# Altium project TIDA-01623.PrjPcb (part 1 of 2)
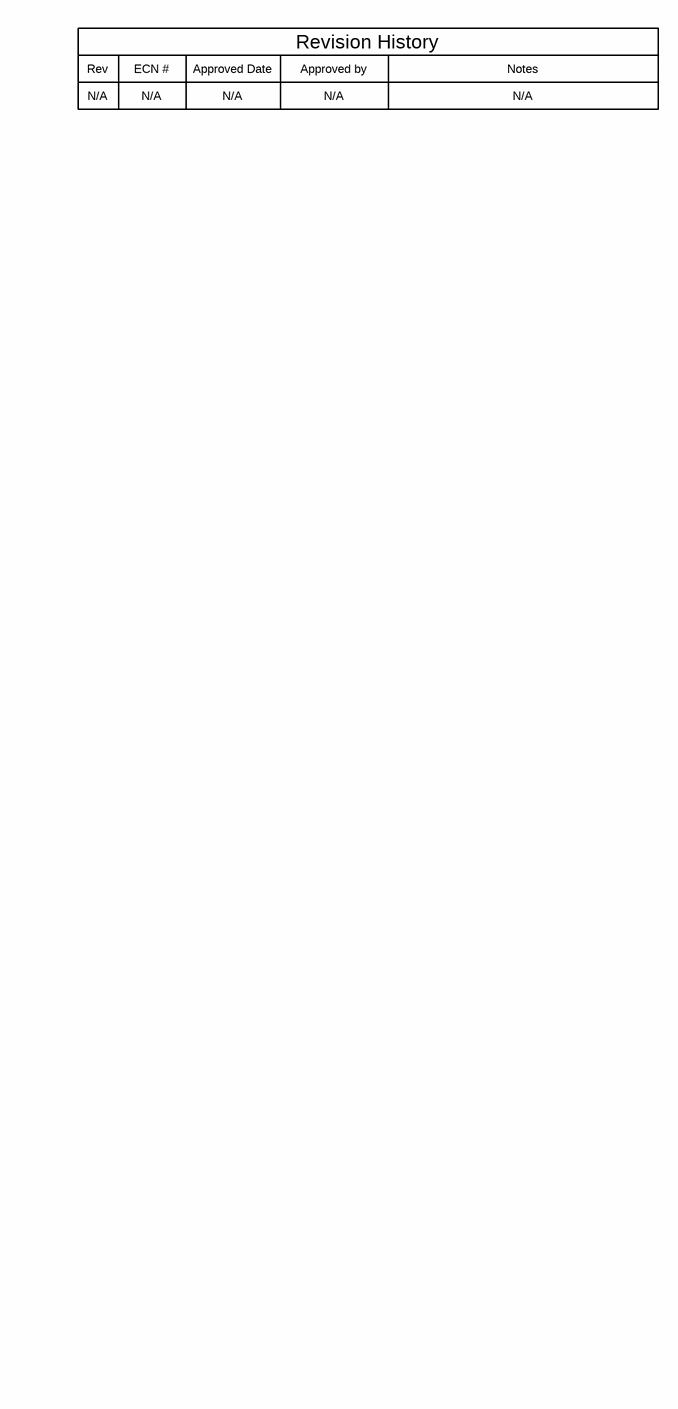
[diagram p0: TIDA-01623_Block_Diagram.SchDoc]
CopyrightYear: 2017; EVM_orderable: N/A; PCB_Layout: Akshay Labhe; PCB_Rev: E1; PRJ_Customer: Public Release; PRJ_Engineer: Cheng Liu; PRJ_Number: TIDA-01623; PRJ_Title: 100W AC/DC Adapter; SCH_Rev: E1; TechSupport: http://www.ti.com/support; TID: TIDA-01623
4 sheets, 214 parts. Net scope: flat (ports and power ports of the same name join across sheets).
Board file: TIDA-01623.PcbDoc
Sheets:
  TIDA-01623_Block_Diagram.SchDoc
  TIDA-01623_PFC_Stage.SchDoc
  TIDA-01623-ACF_Stage.SchDoc
  TIDA-01623_Hardware.SchDoc

## Sheet TIDA-01623_Block_Diagram.SchDoc: Block Diagram
size 431 x 279 mm; Date: Not shown in title block; ApprovedBy: Not shown in title block; CheckedBy: Not shown in title block; Author: Not shown in title block; CompanyName: Not shown in title block; DrawnBy: Cheng Liu; Engineer: Cheng Liu; Organization: Not shown in title block; Address1: Not shown in title block; Address2: Not shown in title block; Address3: Not shown in title block; Address4: Not shown in title block; DocumentNumber: 1; Revision: Use project parameter SCH_Rev; SheetNumber: 1; SheetTotal: 4; PageSetup: Record=PageOptions¦CenterHorizontal=True¦CenterVertical=True¦PrintScale=1.00¦XCorrection=1.00¦YCorrection=1.00¦PrintKind=0¦BorderSize=5000000¦LeftOffset=0¦BottomOffset=0¦Orientation=2¦PaperLength=1000¦PaperWidth=1000¦Scale=100¦PaperSource=15¦PrintQuality=600¦MediaType=1¦DitherType=10¦PaperKind=Letter¦PrintScaleMode=1

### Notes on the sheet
- Rev
- N/A
- ECN #
- Approved Date
- Approved by
- Revision History
- Notes

## Sheet TIDA-01623_PFC_Stage.SchDoc
size 431 x 279 mm; Date: Not shown in title block; ApprovedBy: Not shown in title block; CheckedBy: Not shown in title block; Author: Not shown in title block; CompanyName: Not shown in title block; Engineer: Not shown in title block; Organization: Not shown in title block; Address1: Not shown in title block; Address2: Not shown in title block; Address3: Not shown in title block; Address4: Not shown in title block; DocumentNumber: 1; Revision: Use project parameter SCH_Rev; SheetNumber: 2; SheetTotal: 4; PageSetup: Record=PageOptions¦CenterHorizontal=True¦CenterVertical=True¦PrintScale=1.00¦XCorrection=1.00¦YCorrection=1.00¦PrintKind=0¦BorderSize=5000000¦LeftOffset=0¦BottomOffset=0¦Orientation=2¦PaperLength=1000¦PaperWidth=1000¦Scale=100¦PaperSource=15¦PrintQuality=600¦MediaType=1¦DitherType=10¦PaperKind=Letter¦PrintScaleMode=1
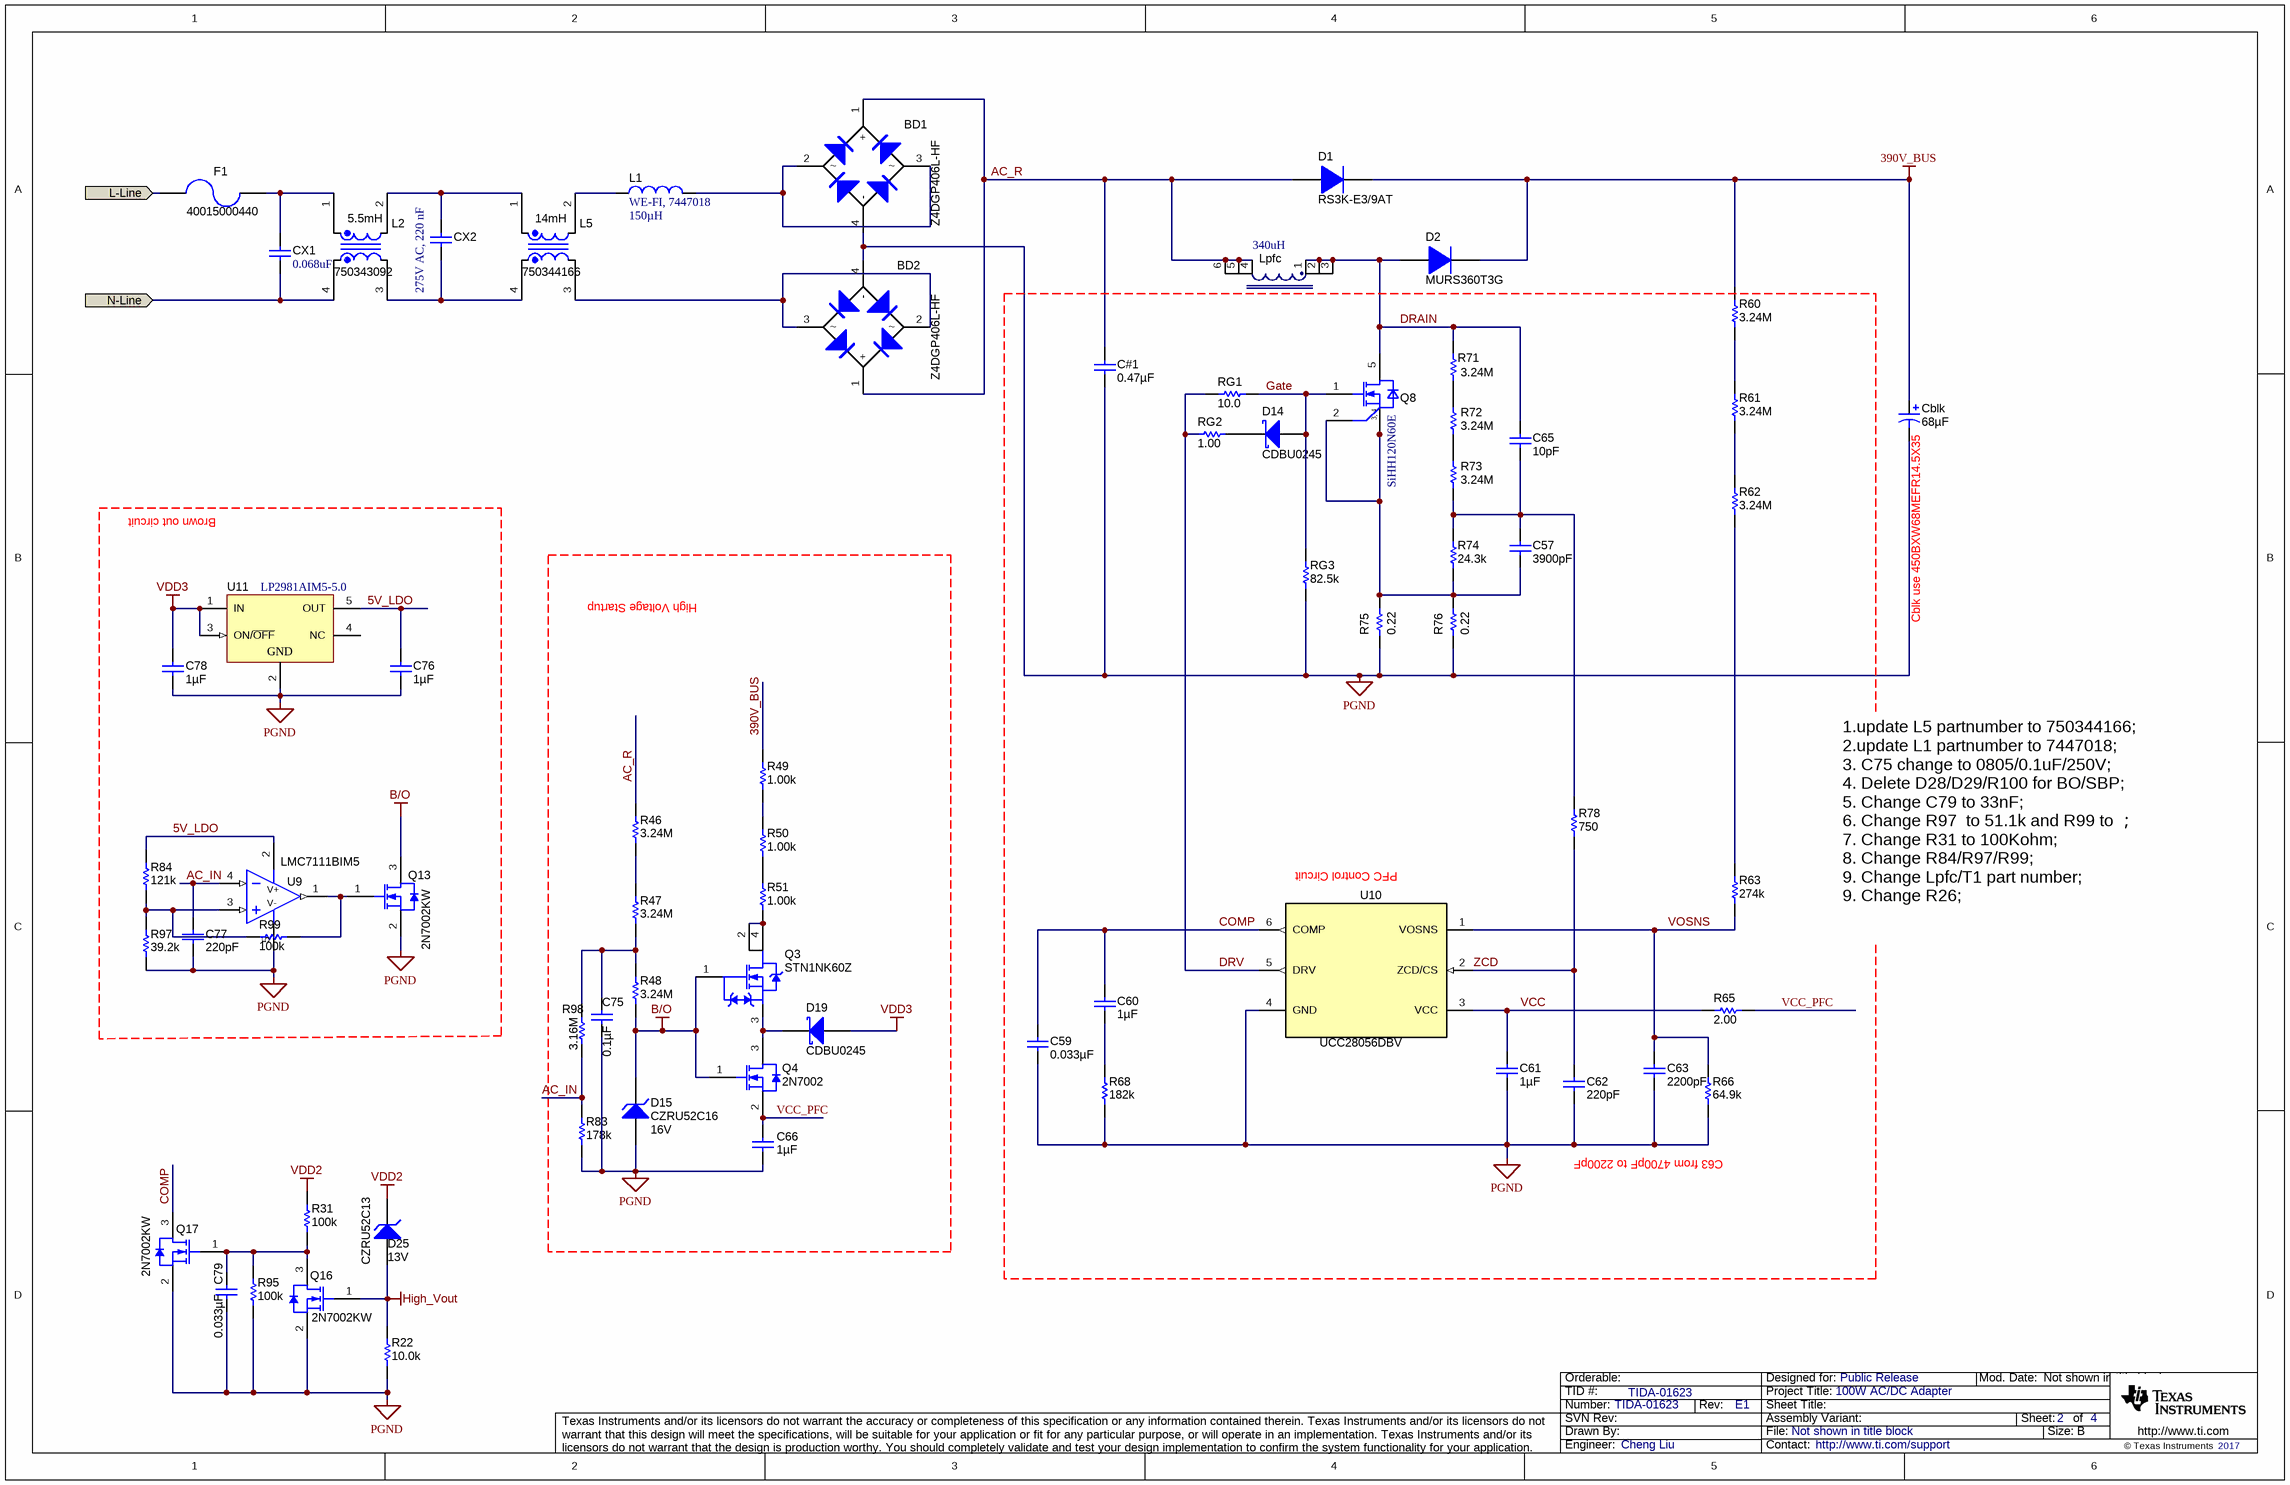
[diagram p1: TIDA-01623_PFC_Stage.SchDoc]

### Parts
BD1  Z4DGP406L-HF  [Z4-D]
BD2  Z4DGP406L-HF  [Z4-D]
C57  ValueDisplayed: 3900pF  [0603]  (hidden comment: GRM188R72A392KA01D)
C59  ValueDisplayed: 0.033µF  [0603S]  (hidden comment: GRM188R71H333KA61D)
C60  ValueDisplayed: 1µF  [0603]  (hidden comment: GRM188R71E105KA12D)
C61  ValueDisplayed: 1µF  [0603]  (hidden comment: UMK107AB7105KA-T)
C62  ValueDisplayed: 220pF  [0603]  (hidden comment: GRM1885C1H221JA01D)
C63  ValueDisplayed: 2200pF  [0603S]  (hidden comment: GRM1885C1H222JA01D)
C65  ValueDisplayed: 10pF  [1206]  (hidden comment: VJ1206A100JXGAT5Z)
C66  ValueDisplayed: 1µF  [0805_HV1]  (hidden comment: C0805C105K3RACTU)
C75  ValueDisplayed: 0.1µF  [0805_HV]  (hidden comment: C2012X7T2E104K125AA)
C76  ValueDisplayed: 1µF  [0603S]  (hidden comment: UMK107AB7105KA-T)
C77  ValueDisplayed: 220pF  [0603S]  (hidden comment: GRM1885C1H221JA01D)
C78  ValueDisplayed: 1µF  [0603S]  (hidden comment: UMK107AB7105KA-T)
C79  ValueDisplayed: 0.033µF  [0402]  (hidden comment: GRM155R71E333KA88D)
C#1  ValueDisplayed: 0.47µF  [ECWFD_1260x650x1270]  (hidden comment: ECW-FD2W474Q1)
Cblk  ValueDisplayed: 68µF  [PCBComponent_1]  (hidden comment: 420BXW68MEFC14.5X35)
CX1  0.068uF  [WCAP-FTX2_10x6x12]
CX2  275V AC, 220 nF  [PCBComponent_1]
D1  RS3K-E3/9AT  [SMC]
D2  MURS360T3G  [SMC]
D14  CDBU0245  [SOD-523F]
D15  CZRU52C16  value 16V  [SOD-523F]
D19  CDBU0245  [SOD-523F]
D25  CZRU52C13  value 13V  [SOD-523F]
F1  40015000440  [FUSE_392]
L1  WE-FI, 7447018  value 150µH  [PCBComponent_1]
L2  750343092  ValueDisplayed: 5.5mH  [750311982]
L5  750344166  ValueDisplayed: 14mH  [PCBComponent_1]
Lpfc  340uH  [RM4_5754]
Q3  STN1NK60Z  [SOT-223]
Q4  2N7002  [SOT-23]
Q8  SiHH120N60E  [INF-PG-VSON-4]
Q13  2N7002KW  [SOT-323]
Q16  2N7002KW  [SOT-323]
Q17  2N7002KW  [SOT-323]
R22  ValueDisplayed: 10.0k  [0402]  (hidden comment: CRCW040210K0FKED)
R31  ValueDisplayed: 100k  [0402]  (hidden comment: CRCW0402100KFKED)
R46  ValueDisplayed: 3.24M  [1206]  (hidden comment: CRCW12063M24FKEA)
R47  ValueDisplayed: 3.24M  [1206]  (hidden comment: CRCW12063M24FKEA)
R48  ValueDisplayed: 3.24M  [1206]  (hidden comment: CRCW12063M24FKEA)
R49  ValueDisplayed: 1.00k  [1206]  (hidden comment: CRCW12061K00FKEA)
R50  ValueDisplayed: 1.00k  [1206]  (hidden comment: CRCW12061K00FKEA)
R51  ValueDisplayed: 1.00k  [1206]  (hidden comment: CRCW12061K00FKEA)
R60  ValueDisplayed: 3.24M  [1206]  (hidden comment: CRCW12063M24FKEA)
R61  ValueDisplayed: 3.24M  [1206]  (hidden comment: CRCW12063M24FKEA)
R62  ValueDisplayed: 3.24M  [1206]  (hidden comment: CRCW12063M24FKEA)
R63  ValueDisplayed: 274k  [0603]  (hidden comment: CRCW0603274KFKEA)
R65  ValueDisplayed: 2.00  [0603]  (hidden comment: CRCW06032R00FKEA)
R66  ValueDisplayed: 64.9k  [0603S]  (hidden comment: CRCW060364K9FKEA)
R68  ValueDisplayed: 182k  [0402]  (hidden comment: CRCW0402182KFKED)
R71  ValueDisplayed: 3.24M  [1206]  (hidden comment: CRCW12063M24FKEA)
R72  ValueDisplayed: 3.24M  [1206]  (hidden comment: CRCW12063M24FKEA)
R73  ValueDisplayed: 3.24M  [1206]  (hidden comment: CRCW12063M24FKEA)
R74  ValueDisplayed: 24.3k  [0603]  (hidden comment: RT0603DRE0724K3L)
R75  ValueDisplayed: 0.22  [1206]  (hidden comment: ERJ-8RQFR22V)
R76  ValueDisplayed: 0.22  [1206]  (hidden comment: ERJ-8RQFR22V)
R78  ValueDisplayed: 750  [0603]  (hidden comment: CRCW0603750RFKEA)
R83  ValueDisplayed: 178k  [0402]  (hidden comment: CRCW0402178KFKED)
R84  ValueDisplayed: 121k  [0402]  (hidden comment: CRCW0402121KFKED)
R95  ValueDisplayed: 100k  [0402]  (hidden comment: CRCW0402100KFKED)
R97  ValueDisplayed: 39.2k  [0402]  (hidden comment: CRCW040239K2FKED)
R98  ValueDisplayed: 3.16M  [0805_HV]  (hidden comment: CRCW08053M16FKEA)
R99  ValueDisplayed: 100k  [0402]  (hidden comment: CRCW0402100KFKED)
RG1  ValueDisplayed: 10.0  [0603]  (hidden comment: CRCW060310R0FKEA)
RG2  ValueDisplayed: 1.00  [0603]  (hidden comment: CRCW06031R00FKEA)
RG3  ValueDisplayed: 82.5k  [0603]  (hidden comment: CRCW060382K5FKEA)
U9  LMC7111BIM5  [DBV0005A_N]
U10  UCC28056DBV  [DBV0006A_N]
U11  LP2981AIM5-5.0  [MF05A_N]

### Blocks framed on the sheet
Brown out circuit: C76-C78 Q13 R84 R97 R99 U9 U11
High Voltage Startup: C66 C75 D15 D19 Q3 Q4 R46-R51 R83 R98

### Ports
L-Line, N-Line

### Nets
390V_BUS: Cblk.1(+) D1.1(K) D2.1(K) R49.1 R60.2
B/O: D15.1(K) Q3.1(G) Q4.1(G) Q13.3(D) R48.1
High_Vout: D25.2(A) Q16.1(G) R22.1
PGND: BD1.4(-) BD2.4(-) C59.2 C61.2 C62.1 C63.1 C66.2 C75.2 C76.1 C77.2 C78.1 C79.2 C#1.2 Cblk.2(-) D15.2(A) Q13.2(S) Q16.2(S) Q17.2(S) R22.2 R66.1 R68.1 R75.1 R76.1 R83.2 R95.2 R97.1 RG3.1 U9.5(V-) U10.4(GND) U11.2(GND)
VDD2: D25.1(K) R31.1
VDD3: C78.2 D19.2(A) U11.1(IN) U11.3(ON/~{OFF})
5V_LDO: C76.2 R84.2 U9.2(V+) U11.5(OUT)
AC_IN: C77.1 R83.1 R98.1 U9.4(IN-)
AC_R: BD1.1(+) BD2.1(+) C#1.1 D1.2(A) Lpfc.4 Lpfc.5 Lpfc.6 R46.2
COMP: C59.1 C60.1 Q17.3(D) U10.6(COMP)
DRAIN: C65.1 D2.2(A) Lpfc.1 Lpfc.2 Lpfc.3 Q8.5(DRAIN) R71.2
DRV: RG1.1 RG2.1 U10.5(DRV)
Gate: D14.2(A) Q8.1(GATE) RG1.2 RG3.2
L-Line: F1.2 ; port L-Line
N-Line: CX1.1 L2.4 ; port N-Line
VCC: C61.1 R65.1 U10.3(VCC)
VCC_PFC: C66.1 Q4.2(S) R65.2
VOSNS: C63.2 R63.1 R66.2 U10.1(VOSNS)
ZCD: C62.2 R78.1 U10.2(ZCD/CS)
NetBD1_2: BD1.2 BD1.3 L1.2
NetBD2_2: BD2.2 BD2.3 L5.3
NetC57_1: C57.1 C65.2 R73.1 R74.2 R78.2
NetC57_2: C57.2 Q8.2(SOURCE) Q8.3(SOURCE) Q8.4(SOURCE) R74.1 R75.2 R76.2
NetC60_2: C60.2 R68.2
NetC75_1: C75.1 R47.1 R48.2 R98.2
NetC79_1: C79.1 Q16.3(D) Q17.1(G) R31.2 R95.1
NetCX1_2: CX1.2 F1.1 L2.1
NetCX2_1: CX2.1 L2.3 L5.4
NetCX2_2: CX2.2 L2.2 L5.1
NetD14_1: D14.1(K) RG2.2
NetD19_1: D19.1(K) Q3.3(S) Q4.3(D)
NetL1_1: L1.1 L5.2
NetQ3_2: Q3.2(D) Q3.4(D) R51.2
NetQ13_1: Q13.1(G) R99.1 U9.1(OUT)
NetR46_1: R46.1 R47.2
NetR49_2: R49.2 R50.1
NetR50_2: R50.2 R51.1
NetR60_1: R60.1 R61.2
NetR61_1: R61.1 R62.2
NetR62_1: R62.1 R63.2
NetR71_1: R71.1 R72.2
NetR72_1: R72.1 R73.2
NetR84_1: R84.1 R97.2 R99.2 U9.3(IN+)

Not connected (* = marked no-connect by the designer): U11 4(NC)

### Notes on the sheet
- (near Cblk) Cblk use 450BXW68MEFR14.5X35
- (near U10) PFC Control Circuit
- 1.update L5 partnumber to 750344166;
  2.update L1 partnumber to 7447018;
  3. C75 change to 0805/0.1uF/250V;
  4. Delete D28/D29/R100 for BO/SBP;
  5. Change C79 to 33nF;
  6. Change R97  to 51.1k and R99 to ；
  7. Change R31 to 100Kohm;
  8. Change R84/R97/R99;
  9. Change Lpfc/T1 part number;
  9. Change R26;
- C63 from 4700pF to 2200pF

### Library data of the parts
BD1 BD2 = Z4DGP406L-HF: Diode, P-N-Bridge, 600 V, 4 A, Z4-D; Manufacturer: Comchip Technology; U/M: EA; Vf_V: 0.95; Value: 600V; Value1: 4A; Value2: 0.95V; Io_A: 4; Vr_V: 600; TJmax_C: 175; SizeAreaWB_mm2: 126.25; SizeArea_mm2: 85.05; SizeX_mm: 10.5; SizeY_mm: 8.1; SizeZ_mm: 1.55; AEC Category: Q101; AEC Qualified: N
C57 = GRM188R72A392KA01D: CAP, CERM, 3900 pF, 100 V,+/- 10%, X7R, 0603; Manufacturer: MuRata; Polarized: N; CompType: Capacitor; Value: 3900pF; U/M: EA; Cap_F: 0.0000000039; Tolerance_%: 10; VDC_V: 100; Value2: 100V; TaMin_C: -55; TaMax_C: 125; SizeArea_mm2: 1.28; SizeAreaWB_mm2: 4.68; SizeX_mm: 1.6; SizeY_mm: 0.8; SizeZ_mm: 1; AEC Category: Q200
C59 = GRM188R71H333KA61D: CAP, CERM, 0.033 µF, 50 V, +/- 10%, X7R, 0603; Manufacturer: MuRata; Polarized: N; CompType: Capacitor; Value: 0.033uF; U/M: EA; Cap_F: 0.000000033; Tolerance_%: 10; Value1: Unknown; VDC_V: 50; Value2: 50V; TaMin_C: -55; TaMax_C: 125; Cap_Case: 0603; SizeArea_mm2: 1.28; SizeAreaWB_mm2: 4.68; SizeX_mm: 1.6; SizeY_mm: 0.8; SizeZ_mm: 1; AEC Category: Q200
C60 = GRM188R71E105KA12D: CAP, CERM, 1 µF, 25 V, +/- 10%, X7R, 0603; Manufacturer: MuRata; Polarized: N; CompType: Capacitor; Value: 1uF; U/M: EA; Cap_F: 0.000001; Tolerance_%: 10; Value1: Unknown; VDC_V: 25; Value2: 25V; TaMin_C: -55; TaMax_C: 125; SizeArea_mm2: 1.28; SizeAreaWB_mm2: 4.68; SizeX_mm: 1.6; SizeY_mm: 0.8; SizeZ_mm: 1; AEC Category: Q200
C61 = UMK107AB7105KA-T: CAP, CERM, 1 µF, 50 V, +/- 10%, X7R, 0603; Manufacturer: Taiyo Yuden; Polarized: N; CompType: Capacitor; Value: 1uF; U/M: EA; Cap_F: 0.000001; Tolerance_%: 10; Value1: Unknown; VDC_V: 50; Value2: 50V; TaMin_C: -55; TaMax_C: 125; SizeArea_mm2: 1.28; SizeAreaWB_mm2: 4.68; SizeX_mm: 1.6; SizeY_mm: 0.8; SizeZ_mm: 1; AEC Category: Q200
C62 = GRM1885C1H221JA01D: CAP, CERM, 220 pF, 50 V, +/- 5%, C0G/NP0, 0603; Manufacturer: MuRata; Polarized: N; CompType: Capacitor; Value: 220pF; U/M: EA; Cap_F: 0.00000000022; Tolerance_%: 5; Value1: Unknown; VDC_V: 50; Value2: 50V; TaMin_C: -55; TaMax_C: 125; SizeArea_mm2: 1.28; SizeAreaWB_mm2: 4.68; SizeX_mm: 1.6; SizeY_mm: 0.8; SizeZ_mm: 1; AEC Category: Q200
C63 = GRM1885C1H222JA01D: CAP, CERM, 2200 pF, 50 V, +/- 5%, C0G/NP0, 0603; Manufacturer: MuRata; Polarized: N; CompType: Capacitor; Value: 2200pF; U/M: EA; Cap_F: 0.0000000022; Tolerance_%: 5; Value1: Unknown; VDC_V: 50; Value2: 50V; TaMin_C: -55; TaMax_C: 125; Cap_Case: 0603; SizeArea_mm2: 1.28; SizeAreaWB_mm2: 4.68; SizeX_mm: 1.6; SizeY_mm: 0.8; SizeZ_mm: 1; AEC Category: Q200
C65 = VJ1206A100JXGAT5Z: CAP, CERM, 10 pF, 1000 V, +/- 5%, C0G/NP0, 1206; Manufacturer: Vishay-Vitramon; Polarized: N; CompType: Capacitor; Value: 10pF; U/M: EA; Cap_F: 0.00000000001; Tolerance_%: 5; Value1: Unknown; VDC_V: 1000; Value2: 1000V; TaMin_C: -55; TaMax_C: 125; SizeArea_mm2: 5.12; SizeAreaWB_mm2: 10.92; SizeX_mm: 3.2; SizeY_mm: 1.6; SizeZ_mm: 1.35; AEC Category: Q200
C66 = C0805C105K3RACTU: CAP, CERM, 1 µF, 25 V, +/- 10%, X7R, 0805; Manufacturer: Kemet; Polarized: N; CompType: Capacitor; Value: 1uF; U/M: EA; Cap_F: 0.000001; Tolerance_%: 10; Value1: Unknown; VDC_V: 25; Value2: 25V; TaMin_C: -55; TaMax_C: 125; Cap_Case: 0805; SizeArea_mm2: 2.5; SizeAreaWB_mm2: 6.75; SizeX_mm: 2; SizeY_mm: 1.25; SizeZ_mm: 1.45; AEC Category: Q200
C75 = C2012X7T2E104K125AA: CAP, CERM, 0.1 µF, 250 V, +/- 10%, X7T, 0805; Manufacturer: TDK; Polarized: N; CompType: Capacitor; Value: 0.1uF; U/M: EA; Cap_F: 0.0000001; Tolerance_%: 10; Value1: Unknown; VDC_V: 250; Value2: 250V; TaMin_C: -55; TaMax_C: 125; Cap_Case: 0805; SizeArea_mm2: 2.5; SizeAreaWB_mm2: 6.75; SizeX_mm: 2; SizeY_mm: 1.25; SizeZ_mm: 1.45; AEC Category: Q200
C76 C78 = UMK107AB7105KA-T: CAP, CERM, 1 µF, 50 V, +/- 10%, X7R, 0603; Manufacturer: Taiyo Yuden; Polarized: N; CompType: Capacitor; Value: 1uF; U/M: EA; Cap_F: 0.000001; Tolerance_%: 10; Value1: Unknown; VDC_V: 50; Value2: 50V; TaMin_C: -55; TaMax_C: 125; Cap_Case: 0603; SizeArea_mm2: 1.28; SizeAreaWB_mm2: 4.68; SizeX_mm: 1.6; SizeY_mm: 0.8; SizeZ_mm: 1; AEC Category: Q200
C77 = GRM1885C1H221JA01D: CAP, CERM, 220 pF, 50 V, +/- 5%, C0G/NP0, 0603; Manufacturer: MuRata; Polarized: N; CompType: Capacitor; Value: 220pF; U/M: EA; Cap_F: 0.00000000022; Tolerance_%: 5; Value1: Unknown; VDC_V: 50; Value2: 50V; TaMin_C: -55; TaMax_C: 125; Cap_Case: 0603; SizeArea_mm2: 1.28; SizeAreaWB_mm2: 4.68; SizeX_mm: 1.6; SizeY_mm: 0.8; SizeZ_mm: 1; AEC Category: Q200
C79 = GRM155R71E333KA88D: CAP, CERM, 0.033 µF, 25 V, +/- 10%, X7R, 0402; Manufacturer: MuRata; Polarized: N; CompType: Capacitor; Value: 0.033uF; U/M: EA; Cap_F: 0.000000033; Tolerance_%: 10; Value1: Unknown; VDC_V: 25; Value2: 25V; TaMin_C: -55; TaMax_C: 125; SizeArea_mm2: 0.5; SizeAreaWB_mm2: 3; SizeX_mm: 1; SizeZ_mm: 0.6; AEC Category: Q200
C#1 = ECW-FD2W474Q1: CAP, Film, 0.47 µF, 450 V, +/- 10%, TH; Manufacturer: Panasonic; Polarized: N; CompType: Capacitor; Value: 0.47uF; U/M: EA; Cap_F: 0.00000047; Tolerance_%: 10; Value1: Unknown; VDC_V: 450; Value2: 450V; TaMin_C: -40; TaMax_C: 110; Cap_Case: 12.6x6.5x12.7mm; AEC Category: Q200
Cblk = 450BXW68MEFC12.5X45: CAP, AL, 68 µF, 420 V, +/- 20%, TH; Manufacturer: Rubycon; Polarized: Y; CompType: Capacitor; Value: 68uF; U/M: EA; Cap_F: 0.000068; Tolerance_%: 20; Value1: Unknown; VDC_V: 450; Value2: 450V; IRMS_A: 0.61; TaMin_C: -40; TaMax_C: 105; Cap_Case: 12.5X45mm; SizeAreaWB_mm2: 210.25; SizeArea_mm2: 156.25; SizeX_mm: 12.5; SizeZ_mm: 47; AEC Category: Q200; AEC Qualified: N
CX1 = 890324022017: WCAP-FTX2 Film Capacitors, 10x6x12mm, 275V AC, 68 nF; Value: 68 nF; Rated Voltage: 275V AC
CX2 = 890324024002: WCAP-FTX2 Film Capacitors, 15x7x12.5mm, 275V AC, 220 nF; Value: 220 nF; Rated Voltage: 275V AC
D1 = RS3K-E3/9AT: Diode, Switching, 800 V, 3 A, SMC; Manufacturer: Vishay-Semiconductor; U/M: EA; Vf_V: 1.3; Value: 800V; Value1: 3A; Value2: 1.3V; Io_A: 3; Vr_V: 800; TJmax_C: 150; RJC_CperW: 50; SizeAreaWB_mm2: 83.2686; SizeArea_mm2: 50.5686; SizeX_mm: 8.13; SizeY_mm: 6.22; SizeZ_mm: 2.6; AEC Category: Q101
D2 = MURS360T3G: Diode, Ultrafast, 600 V, 3 A, SMC; Manufacturer: ON Semiconductor; U/M: EA; Vf_V: 1.25; Value: 600V; Value1: 3A; Value2: 1.25V; Io_A: 3; Vr_V: 600; TJmax_C: 175; RJC_CperW: 11; SizeAreaWB_mm2: 83.2686; SizeArea_mm2: 50.5686; SizeX_mm: 8.13; SizeY_mm: 6.22; SizeZ_mm: 2.6; AEC Category: Q101
D14 D19 = CDBU0245: Diode, Schottky, 50 V, 0.2 A, SOD-523F; Manufacturer: Comchip Technology; U/M: EA; Vf_V: 0.55; Value: 50V; Value1: 0.2A; Value2: 0.55V; Io_A: 0.2; Vr_V: 50; TJmax_C: 125; SizeAreaWB_mm2: 5.13; SizeArea_mm2: 1.53; SizeX_mm: 1.7; SizeY_mm: 0.9; SizeZ_mm: 0.85; AEC Category: Q101; AEC Qualified: N
D15 = CZRU52C5V6: Diode, Zener, 16 V, 150 mW, SOD-523F; Manufacturer: Comchip Technology; U/M: EA; Power_W: 0.15; Vz_V: 16; Value1: 0.15W; SizeAreaWB_mm2: 5.13; SizeArea_mm2: 1.53; SizeX_mm: 1.7; SizeY_mm: 0.9; SizeZ_mm: 0.85; AEC Category: Q101; SymbolCreator: a0412235
D25 = CZRU52C5V6: Diode, Zener, 11 V, 150 mW, SOD-523F; Manufacturer: Comchip Technology; U/M: EA; Power_W: 0.15; Vz_V: 13; Value1: 0.15W; SizeAreaWB_mm2: 5.13; SizeArea_mm2: 1.53; SizeX_mm: 1.7; SizeY_mm: 0.9; SizeZ_mm: 0.85; AEC Category: Q101; SymbolCreator: a0412235
F1 = 39213150000: Fuse, 5 A, 250VAC/VDC, TH; Manufacturer: Littelfuse; VDC_V: 250; Irating_A: 5; Green_Lifecycle: Active; Green_REACh: Passed
L1 = WE-FI, 7447031: WE-FI Leaded Toroidal Line Choke, L = 140µH; Manufacturer: Wurth Elektronik
L2 = 744823210: Coupled inductor, 5.5mH+/-32%, 2.5 A, 0.040 ohm; Manufacturer: Wurth Elektronik; Value: 5.5mH=/-32%; Ind_H: 5.5e-3; Tolerance_%: 32
L5 = 744823210: Coupled inductor, 5.5mH+/-32%, 2.5 A, 0.040 ohm; Manufacturer: Wurth Elektronik; Value: 14mH; Ind_H: 5.5e-3; Tolerance_%: 32
Lpfc = RM4, 070-5754: Transformer 6-Terminal , THT, Vertical, RM10; PartNo: 750343984; Manufacturer: Würth Elektronik Midcom; Core: 150-2620
Q3 = STN3N40K3: MOSFET, N-CH, 600 V, 0.3 A, SOT-223; Manufacturer: STMicroelectronics; Alternate Manufacturer: None; U/M: EA; ChType: N; Value: 600V; VdsMax_V: 400; Value1: 15 ohm; Rdson45_ohm: 3; Value2: 11 nC; QgTyp_nC: 11; Vgs_V: 30; IdsMax_A: 0.3; SizeAreaWB_mm2: 76.5; SizeArea_mm2: 45.5; SizeX_mm: 6.5; SizeY_mm: 7; SizeZ_mm: 1.6; AEC Category: Q101; SymbolCreator: a0411947
Q4 = 2N7002: MOSFET, N-CH, 60 V, 115 A, SOT-23; Manufacturer: Fairchild Semiconductor; Alternate Manufacturer: None; U/M: EA; ChType: N; Value: 60V; VdsMax_V: 60; Value1: ? ohm; Value2: ? nC; Vgs_V: 20; IdsMax_A: 115; SizeAreaWB_mm2: 14; SizeArea_mm2: 7.5; SizeX_mm: 2.5; SizeY_mm: 3; SizeZ_mm: 1.1; AEC Category: Q101
Q8 = IPL65R099C7: 'N-Channel 600V 24A (Tc) 156W (Tc) Surface Mount PowerPAK® 8 x 8; Manufacturer: Infineon Technologies
Q13 Q16 Q17 = 2N7002KW: MOSFET, N-CH, 60 V, 0.31 A, SOT-323; Manufacturer: Fairchild Semiconductor; Alternate Manufacturer: None; U/M: EA; ChType: N; Value: 60V; VdsMax_V: 60; Value1: 1.6 ohm; Rdson45_ohm: 1.6; Value2: ? nC; Vgs_V: 2.1; IdsMax_A: 0.31; SizeAreaWB_mm2: 10.24; SizeArea_mm2: 4.84; SizeX_mm: 2.2; SizeZ_mm: 1.1; AEC Category: Q101
R22 = CRCW040210K0FKED: RES, 10.0 k, 1%, 0.063 W, 0402; Manufacturer: Vishay-Dale; CompType: Resistor; Value: 10.0k; Res_ohm: 10000; Value_Code: 10k0; Tolerance_%: 1; Power_W: 0.063; Value2: 0.063W; VDC_V: 50; TempCo: 100 ppm/C; SizeArea_mm2: 0.5; SizeZ_mm: 0.6; EIA_Code: E96; U/M: EA; AEC Category: Q200
R31 R95 R99 = CRCW0402100KFKED: RES, 100 k, 1%, 0.063 W, 0402; Manufacturer: Vishay-Dale; CompType: Resistor; Value: 100k; Res_ohm: 100000; Tolerance_%: 1; Power_W: 0.063; Value2: 0.063W; VDC_V: 50; TempCo: 100 ppm/C; SizeArea_mm2: 0.5; SizeZ_mm: 0.6; EIA_Code: E96; U/M: EA; AEC Category: Q200
R46-R48 R60-R62 R71-R73 = CRCW12063M24FKEA: RES, 3.24 M, 1%, 0.25 W, 1206; Manufacturer: Vishay-Dale; CompType: Resistor; Value: 3.24Meg; Res_ohm: 3240000; Value_Code: 3M24; Tolerance_%: 1; Power_W: 0.25; Value2: 0.25W; VDC_V: 200; TempCo: 100 ppm/C; SizeArea_mm2: 5.12; SizeX_mm: 3.2; SizeY_mm: 1.6; SizeZ_mm: 1.35; EIA_Code: E96; U/M: EA; AEC Category: Q200
R49-R51 = CRCW12061K00FKEA: RES, 1.00 k, 1%, 0.25 W, 1206; Manufacturer: Vishay-Dale; CompType: Resistor; Value: 1.00k; Res_ohm: 1000; Value_Code: 1k00; Tolerance_%: 1; Power_W: 0.25; Value2: 0.25W; VDC_V: 200; TempCo: 100 ppm/C; SizeArea_mm2: 5.12; SizeX_mm: 3.2; SizeY_mm: 1.6; SizeZ_mm: 1.35; EIA_Code: E96; U/M: EA; AEC Category: Q200
R63 = CRCW0603274KFKEA: RES, 274 k, 1%, 0.1 W, 0603; Manufacturer: Vishay-Dale; CompType: Resistor; Value: 274k; Res_ohm: 274000; Tolerance_%: 1; Power_W: 0.1; Value2: 0.1W; VDC_V: 75; TempCo: 100 ppm/C; SizeArea_mm2: 1.28; SizeX_mm: 1.6; SizeY_mm: 0.8; EIA_Code: E96; U/M: EA; AEC Category: Q200
R65 = CRCW06032R00FKEA: RES, 2.00, 1%, 0.1 W, 0603; Manufacturer: Vishay-Dale; CompType: Resistor; Value: 2.00; Res_ohm: 2; Value_Code: 2R00; Tolerance_%: 1; Power_W: 0.1; Value2: 0.1W; VDC_V: 75; TempCo: 100 ppm/C; SizeArea_mm2: 1.28; SizeX_mm: 1.6; SizeY_mm: 0.8; EIA_Code: E96; U/M: EA; AEC Category: Q200
R66 = CRCW060364K9FKEA: RES, 64.9 k, 1%, 0.1 W, 0603; Manufacturer: Vishay-Dale; CompType: Resistor; Value: 64.9k; Res_ohm: 64900; Value_Code: 64k9; Tolerance_%: 1; Power_W: 0.1; Value2: 0.1W; VDC_V: 75; TempCo: 100 ppm/C; SizeArea_mm2: 1.28; SizeX_mm: 1.6; SizeY_mm: 0.8; EIA_Code: E96; U/M: EA; AEC Category: Q200
R68 = CRCW0402182KFKED: RES, 182 k, 1%, 0.063 W, 0402; Manufacturer: Vishay-Dale; CompType: Resistor; Value: 182k; Res_ohm: 182000; Tolerance_%: 1; Power_W: 0.063; Value2: 0.063W; VDC_V: 50; TempCo: 100 ppm/C; SizeArea_mm2: 0.5; SizeZ_mm: 0.6; EIA_Code: E96; U/M: EA; AEC Category: Q200
R74 = RT0603DRE0724K3L: RES, 24.3 k, 0.5%, 0.1 W, 0603; Manufacturer: Yageo America; CompType: Resistor; Value: 24.3k; Res_ohm: 24300; Value_Code: 24k3; Tolerance_%: 0.5; Power_W: 0.1; Value2: 0.1W; VDC_V: 75; TempCo: 50 ppm/C; SizeArea_mm2: 1.28; SizeX_mm: 1.6; SizeY_mm: 0.8; SizeZ_mm: 1; EIA_Code: E192; U/M: EA; AEC Category: Q200
R75 R76 = ERJ-8RQFR22V: RES, 0.22, 1%, 0.25 W, 1206; Manufacturer: Panasonic; CompType: Resistor; Value: 0.22; Value_Code: R220; Tolerance_%: 1; Power_W: 0.25; Value2: 0.25W; TempCo: 250 ppm/C; SizeArea_mm2: 5.12; SizeX_mm: 3.2; SizeY_mm: 1.6; SizeZ_mm: 1.35; EIA_Code: E96; U/M: EA; AEC Category: Q200
R78 = CRCW0603750RFKEA: RES, 750, 1%, 0.1 W, 0603; Manufacturer: Vishay-Dale; CompType: Resistor; Value: 750; Value_Code: 750R; Tolerance_%: 1; Power_W: 0.1; Value2: 0.1W; VDC_V: 75; TempCo: 100 ppm/C; SizeArea_mm2: 1.28; SizeX_mm: 1.6; SizeY_mm: 0.8; EIA_Code: E96; U/M: EA; AEC Category: Q200
R83 = CRCW0402178KFKED: RES, 178 k, 1%, 0.063 W, 0402; Manufacturer: Vishay-Dale; CompType: Resistor; Value: 178k; Res_ohm: 178000; Tolerance_%: 1; Power_W: 0.063; Value2: 0.063W; VDC_V: 50; TempCo: 100 ppm/C; SizeArea_mm2: 0.5; SizeZ_mm: 0.6; EIA_Code: E96; U/M: EA; AEC Category: Q200
R84 = CRCW0402121KFKED: RES, 121 k, 1%, 0.063 W, 0402; Manufacturer: Vishay-Dale; CompType: Resistor; Value: 121k; Res_ohm: 121000; Tolerance_%: 1; Power_W: 0.063; Value2: 0.063W; VDC_V: 50; TempCo: 100 ppm/C; SizeArea_mm2: 0.5; SizeZ_mm: 0.6; EIA_Code: E96; U/M: EA; AEC Category: Q200
R97 = CRCW040239K2FKED: RES, 39.2 k, 1%, 0.063 W, 0402; Manufacturer: Vishay-Dale; CompType: Resistor; Value: 39.2k; Res_ohm: 39200; Value_Code: 39k2; Tolerance_%: 1; Power_W: 0.063; Value2: 0.063W; VDC_V: 50; TempCo: 100 ppm/C; SizeArea_mm2: 0.5; SizeZ_mm: 0.6; EIA_Code: E96; U/M: EA; AEC Category: Q200
R98 = CRCW08053M16FKEA: RES, 3.16 M, 1%, 0.125 W, 0805; Manufacturer: Vishay-Dale; CompType: Resistor; Value: 3.16Meg; Res_ohm: 3160000; Value_Code: 3M16; Tolerance_%: 1; Power_W: 0.125; Value2: 0.125W; VDC_V: 150; TempCo: 100 ppm/C; SizeArea_mm2: 2.5; SizeX_mm: 2; SizeY_mm: 1.25; SizeZ_mm: 1.45; EIA_Code: E96; U/M: EA; AEC Category: Q200
RG1 = CRCW060310R0FKEA: RES, 10.0, 1%, 0.1 W, 0603; Manufacturer: Vishay-Dale; CompType: Resistor; Value: 10.0; Res_ohm: 10; Value_Code: 10R0; Tolerance_%: 1; Power_W: 0.1; Value2: 0.1W; VDC_V: 75; TempCo: 100 ppm/C; SizeArea_mm2: 1.28; SizeX_mm: 1.6; SizeY_mm: 0.8; EIA_Code: E96; U/M: EA; AEC Category: Q200
RG2 = CRCW06031R00FKEA: RES, 1.00, 1%, 0.1 W, 0603; Manufacturer: Vishay-Dale; CompType: Resistor; Value: 1.00; Res_ohm: 1; Value_Code: 1R00; Power_W: 0.1; Value2: 0.1W; VDC_V: 75; TempCo: 100 ppm/C; SizeArea_mm2: 1.28; SizeX_mm: 1.6; SizeY_mm: 0.8; EIA_Code: E96; U/M: EA; AEC Category: Q200
RG3 = CRCW060382K5FKEA: RES, 82.5 k, 1%, 0.1 W, 0603; Manufacturer: Vishay-Dale; CompType: Resistor; Value: 82.5k; Res_ohm: 82500; Value_Code: 82k5; Tolerance_%: 1; Power_W: 0.1; Value2: 0.1W; VDC_V: 75; TempCo: 100 ppm/C; SizeArea_mm2: 1.28; SizeX_mm: 1.6; SizeY_mm: 0.8; EIA_Code: E96; U/M: EA; AEC Category: Q200
U9 = LMC7111BIM5: Tiny CMOS Operational Amplifier with Rail-to-Rail Input and Output, DBV0005A; Manufacturer: Texas Instruments; CompType: OpAmp IC; SymbolCreator: a0411595
U10 = UCC28056DBV: 6-Pin Single-Phase Transition-Mode PFC Controller, DBV0006A (SOT-23-6); Manufacturer: Texas Instruments; SymbolCreator: Altium; SizeArea_mm2: 8.12; SizeAreaWB_mm2: 14.82; SizeX_mm: 2.8; SizeY_mm: 2.9; SizeZ_mm: 1.45; CompType: IC; U/M: EA
U11 = LP2981AIM5-5.0: Micropower 100 mA Ultra Low-Dropout Regulator, 5-pin SOT-23; Manufacturer: Texas Instruments; PackageTopMarking: L03A*XTT; PowerWise: N; CompType: LDO IC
